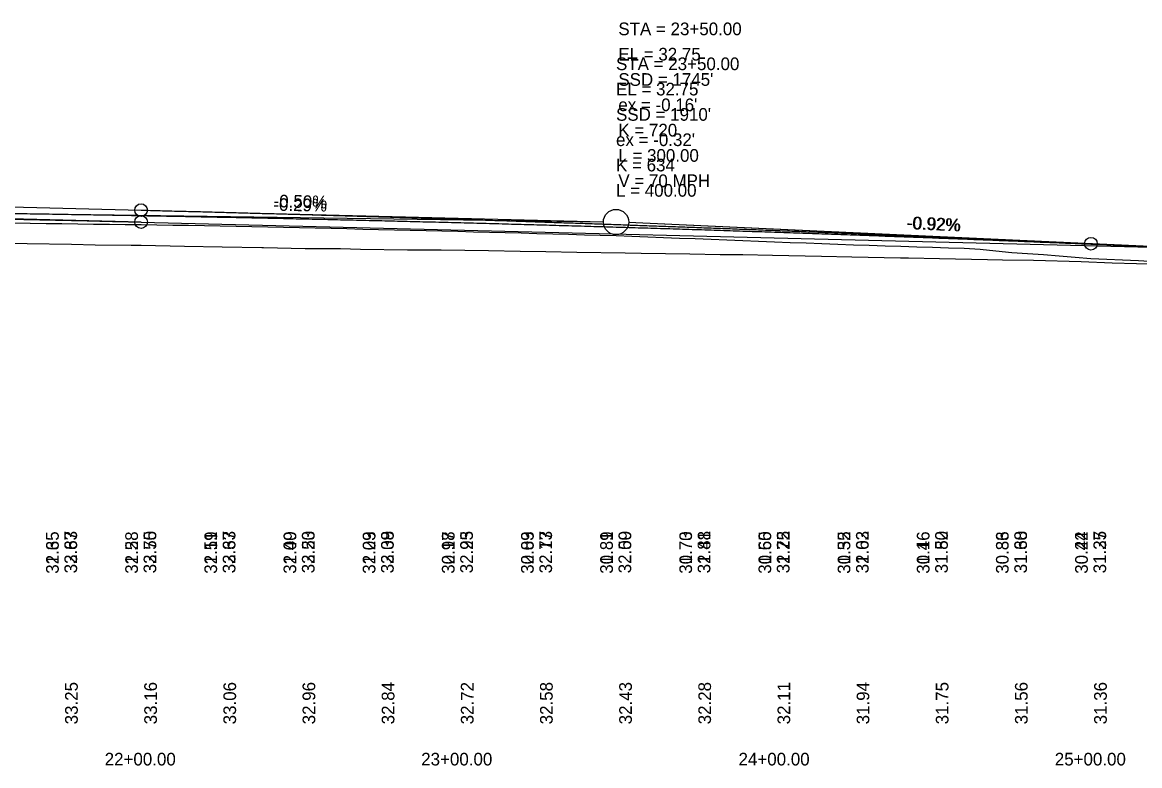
# Model space of a CAD drawing. Extents: x 3880794 to 3915434, y 287517 to 300173.
# Drawn here: x 3882700.8 to 3883053.7, y 296519.7 to 296754.6 of the extents above; entities that cross this region are included whole.
import ezdxf

# ---------------------------------------------------------------- set-up
doc = ezdxf.new("R2010")
doc.units = 0
for name, color, linetype in [('Level 1', 7, 'Continuous'), ('Level 2', 7, 'Continuous'), ('Level 30', 7, 'Continuous'), ('Level 31', 7, 'Continuous'), ('Level 32', 7, 'Continuous')]:
    doc.layers.add(name, color=color, linetype=linetype)

msp = doc.modelspace()

# ---------------------------------------------------------------- linework, layer by layer
at = {"layer": 'Level 1'}
for p, q in [((3882738.3, 296691.51), (3882542.3, 296696.41)), ((3882688.3, 296694.36), (3882884.3, 296691.56)), ((3882738.3, 296691.51), (3883088.3, 296682.76)), ((3883088.3, 296682.34), (3882892.29, 296691.32))]:
    msp.add_line(p, q, dxfattribs=at)
msp.add_lwpolyline([(3882691.39, 296684.85), (3882702.29, 296684.71), (3882716.34, 296684.48), (3882723.78, 296684.35), (3882735.12, 296684.21), (3882738.31, 296684.17), (3882751.98, 296683.92), (3882763.94, 296683.68), (3882776.44, 296683.45), (3882776.96, 296683.44), (3882790.17, 296683.17), (3882801.3, 296683.12), (3882807.64, 296682.98), (3882822.44, 296682.77), (3882832.63, 296682.73), (3882833.04, 296682.73), (3882848.06, 296682.51), (3882858.02, 296682.29), (3882866.12, 296682.17), (3882875.88, 296681.96), (3882891.17, 296681.76), (3882896.22, 296681.65), (3882911.64, 296681.45), (3882921.21, 296681.29), (3882928.3, 296681.2), (3882937.68, 296681.05), (3882953.23, 296680.7), (3882962.8, 296680.54), (3882978.16, 296680.21), (3882980.64, 296680.16), (3882990.44, 296680.02), (3883005.6, 296679.69), (3883010.32, 296679.59), (3883020.14, 296679.45), (3883035.18, 296679.01), (3883044.95, 296678.6), (3883060.37, 296678.16)], dxfattribs=at)
msp.add_circle((3882888.3, 296691.51), 4, dxfattribs=at)
for points in [[(3882338.3, 296690.81), (3882346.3, 296691.03), (3882354.3, 296691.25), (3882362.3, 296691.45), (3882370.3, 296691.65), (3882378.3, 296691.84), (3882386.3, 296692.02), (3882394.3, 296692.19), (3882402.3, 296692.36), (3882410.3, 296692.51), (3882418.3, 296692.66), (3882426.3, 296692.8), (3882434.3, 296692.93), (3882442.3, 296693.05), (3882450.3, 296693.16), (3882458.3, 296693.26), (3882466.3, 296693.36), (3882474.3, 296693.45), (3882482.3, 296693.52), (3882490.3, 296693.59), (3882498.3, 296693.65), (3882506.3, 296693.71), (3882514.3, 296693.75), (3882522.3, 296693.79), (3882530.3, 296693.81), (3882538.3, 296693.83), (3882546.3, 296693.84), (3882554.3, 296693.84), (3882562.3, 296693.84), (3882570.3, 296693.82), (3882578.3, 296693.79), (3882586.3, 296693.76), (3882594.3, 296693.72), (3882602.3, 296693.67), (3882610.3, 296693.61), (3882618.3, 296693.54), (3882626.3, 296693.47), (3882634.3, 296693.38), (3882642.3, 296693.29), (3882650.3, 296693.19), (3882658.3, 296693.08), (3882666.3, 296692.96), (3882674.3, 296692.83), (3882682.3, 296692.7), (3882690.3, 296692.55), (3882698.3, 296692.4), (3882706.3, 296692.24), (3882714.3, 296692.07), (3882722.3, 296691.89), (3882730.3, 296691.7), (3882738.3, 296691.51)], [(3882688.3, 296694.36), (3882696.3, 296694.25), (3882704.3, 296694.13), (3882712.3, 296694), (3882720.3, 296693.87), (3882728.3, 296693.73), (3882736.3, 296693.59), (3882744.3, 296693.44), (3882752.3, 296693.29), (3882760.3, 296693.13), (3882768.3, 296692.97), (3882776.3, 296692.8), (3882784.3, 296692.63), (3882792.3, 296692.45), (3882800.3, 296692.27), (3882808.3, 296692.08), (3882816.3, 296691.89), (3882824.3, 296691.69), (3882832.3, 296691.49), (3882840.3, 296691.28), (3882848.3, 296691.07), (3882856.3, 296690.85), (3882864.3, 296690.63), (3882872.3, 296690.4), (3882880.3, 296690.17), (3882888.3, 296689.93), (3882896.3, 296689.69), (3882904.3, 296689.44), (3882912.3, 296689.19), (3882920.3, 296688.93), (3882928.3, 296688.66), (3882936.3, 296688.4), (3882944.3, 296688.12), (3882952.3, 296687.84), (3882960.3, 296687.56), (3882968.3, 296687.27), (3882976.3, 296686.98), (3882984.3, 296686.68), (3882992.3, 296686.38), (3883000.3, 296686.07), (3883008.3, 296685.75), (3883016.3, 296685.44), (3883024.3, 296685.11), (3883032.3, 296684.78), (3883040.3, 296684.45), (3883048.3, 296684.11), (3883056.3, 296683.77), (3883064.3, 296683.42), (3883072.3, 296683.06), (3883080.3, 296682.7), (3883088.3, 296682.34)]]:
    msp.add_spline(points, degree=3, dxfattribs=at)
at = {"layer": 'Level 2'}
for p, q in [((3882688.3, 296696.51), (3882738.3, 296695.26)), ((3882738.3, 296695.26), (3882884.3, 296691.61)), ((3883038.3, 296684.63), (3882892.29, 296691.32)), ((3883038.3, 296684.63), (3883088.3, 296682.34))]:
    msp.add_line(p, q, dxfattribs=at)
for points in [[(3882698.3, 296691.21), (3882703.3, 296691.15), (3882708.3, 296691.08), (3882713.3, 296691.01), (3882718.3, 296690.95), (3882723.3, 296690.88), (3882728.3, 296690.82), (3882733.3, 296690.75), (3882738.3, 296690.68), (3882743.3, 296690.62), (3882748.3, 296690.55), (3882753.3, 296690.48), (3882758.3, 296690.41), (3882763.3, 296690.3), (3882768.3, 296690.19), (3882773.3, 296690.08), (3882778.3, 296689.97), (3882783.3, 296689.86), (3882788.3, 296689.74), (3882793.3, 296689.63), (3882798.3, 296689.52), (3882803.3, 296689.41), (3882808.3, 296689.3), (3882813.3, 296689.19), (3882818.3, 296689.07), (3882823.3, 296688.96), (3882828.3, 296688.85), (3882833.3, 296688.72), (3882838.3, 296688.58), (3882843.3, 296688.45), (3882848.3, 296688.31), (3882853.3, 296688.17), (3882858.3, 296688.04), (3882863.3, 296687.9), (3882868.3, 296687.76), (3882873.3, 296687.62), (3882878.3, 296687.48), (3882883.3, 296687.34), (3882888.3, 296687.2), (3882893.3, 296687.01), (3882898.3, 296686.82), (3882903.3, 296686.62), (3882908.3, 296686.44), (3882913.3, 296686.25), (3882918.3, 296686.05), (3882923.3, 296685.86), (3882928.3, 296685.66), (3882933.3, 296685.47), (3882938.3, 296685.28), (3882943.3, 296685.08), (3882948.3, 296684.88), (3882953.3, 296684.69), (3882958.3, 296684.5), (3882963.3, 296684.34), (3882968.3, 296684.18), (3882973.3, 296684.02), (3882978.3, 296683.86), (3882983.3, 296683.7), (3882988.3, 296683.54), (3882993.3, 296683.38), (3882998.3, 296683.22), (3883003.3, 296682.96), (3883008.3, 296682.43), (3883013.3, 296681.89), (3883018.3, 296681.58), (3883023.3, 296681.21), (3883028.3, 296680.8), (3883033.3, 296680.39), (3883038.3, 296679.97)], [(3883038.3, 296679.97), (3883043.3, 296679.72), (3883048.3, 296679.51), (3883053.3, 296679.3), (3883058.3, 296679.08)]]:
    msp.add_lwpolyline(points, dxfattribs=at)
for centre, radius in [((3882738.3, 296695.26), 2), ((3882888.3, 296691.51), 4), ((3883038.3, 296684.63), 2)]:
    msp.add_circle(centre, radius, dxfattribs=at)
msp.add_spline([(3882738.3, 296695.26), (3882744.3, 296695.11), (3882750.3, 296694.95), (3882756.3, 296694.8), (3882762.3, 296694.64), (3882768.3, 296694.48), (3882774.3, 296694.31), (3882780.3, 296694.15), (3882786.3, 296693.98), (3882792.3, 296693.81), (3882798.3, 296693.63), (3882804.3, 296693.46), (3882810.3, 296693.28), (3882816.3, 296693.1), (3882822.3, 296692.91), (3882828.3, 296692.73), (3882834.3, 296692.54), (3882840.3, 296692.35), (3882846.3, 296692.15), (3882852.3, 296691.96), (3882858.3, 296691.76), (3882864.3, 296691.56), (3882870.3, 296691.35), (3882876.3, 296691.15), (3882882.3, 296690.94), (3882888.3, 296690.73), (3882894.3, 296690.51), (3882900.3, 296690.3), (3882906.3, 296690.08), (3882912.3, 296689.86), (3882918.3, 296689.63), (3882924.3, 296689.41), (3882930.3, 296689.18), (3882936.3, 296688.95), (3882942.3, 296688.71), (3882948.3, 296688.48), (3882954.3, 296688.24), (3882960.3, 296688), (3882966.3, 296687.75), (3882972.3, 296687.51), (3882978.3, 296687.26), (3882984.3, 296687.01), (3882990.3, 296686.75), (3882996.3, 296686.5), (3883002.3, 296686.24), (3883008.3, 296685.98), (3883014.3, 296685.71), (3883020.3, 296685.45), (3883026.3, 296685.18), (3883032.3, 296684.91), (3883038.3, 296684.63)], degree=3, dxfattribs=at)
at = {"layer": 'Level 31'}
msp.add_circle((3882738.3, 296691.51), 2, dxfattribs=at)

# ---------------------------------------------------------------- texts
at = {"layer": 'Level 2'}
for s, p in [('STA = 23+50.00', (3882889.03, 296750.55)), ('EL = 32.75', (3882889.03, 296742.55)), ("SSD = 1745'", (3882889.03, 296734.55)), ("ex = -0.16'", (3882889.03, 296726.55)), ('K = 720', (3882889.03, 296718.55)), ('L = 300.00', (3882889.03, 296710.55)), ('V = 70 MPH', (3882889.03, 296702.55)), ('22+00.00', (3882726.8, 296519.76)), ('23+00.00', (3882826.77, 296519.76)), ('24+00.00', (3882926.99, 296519.76)), ('25+00.00', (3883026.87, 296519.76))]:
    msp.add_text(s, height=4, dxfattribs=at).set_placement(p)
for s, rotation, p in [('-0.50%', 358.5679, (3882780.1, 296696.21)), ('-0.92%', 357.3758, (3882980.22, 296689.3)), ('33.63', 90, (3882718.09, 296580.49)), ('33.50', 90, (3882743.09, 296580.49)), ('33.37', 90, (3882768.09, 296580.49)), ('33.23', 90, (3882793.09, 296580.49)), ('33.09', 90, (3882818.09, 296580.49)), ('32.93', 90, (3882843.09, 296580.49)), ('32.77', 90, (3882868.09, 296580.49)), ('32.59', 90, (3882893.09, 296580.49)), ('32.41', 90, (3882918.09, 296580.49)), ('32.22', 90, (3882943.09, 296580.49)), ('32.02', 90, (3882968.09, 296580.49)), ('31.82', 90, (3882993.09, 296580.49)), ('31.60', 90, (3883018.09, 296580.49)), ('31.37', 90, (3883043.09, 296580.49))]:
    msp.add_text(s, height=4, rotation=rotation, dxfattribs=at).set_placement(p)
at = {"layer": 'Level 30'}
for s, p in [('31.35', (3882712.3, 296580.35)), ('31.28', (3882737.3, 296580.35)), ('31.19', (3882762.3, 296580.35)), ('31.09', (3882787.3, 296580.35)), ('31.03', (3882812.3, 296580.35)), ('30.98', (3882837.3, 296580.35)), ('30.89', (3882862.3, 296580.35)), ('30.81', (3882887.3, 296580.35)), ('30.73', (3882912.3, 296580.35)), ('30.65', (3882937.3, 296580.35)), ('30.55', (3882962.3, 296580.35)), ('30.46', (3882987.3, 296580.35)), ('30.36', (3883012.3, 296580.35)), ('30.22', (3883037.3, 296580.35))]:
    msp.add_text(s, height=4, rotation=90, dxfattribs=at).set_placement(p)
for s, p in [('22+00.00', (3882726.8, 296519.76)), ('22+00.00', (3882726.8, 296519.76)), ('22+00.00', (3882726.8, 296519.76)), ('23+00.00', (3882826.77, 296519.76)), ('23+00.00', (3882826.77, 296519.76)), ('23+00.00', (3882826.77, 296519.76)), ('24+00.00', (3882926.99, 296519.76)), ('24+00.00', (3882926.99, 296519.76)), ('24+00.00', (3882926.99, 296519.76)), ('25+00.00', (3883026.87, 296519.76)), ('25+00.00', (3883026.87, 296519.76)), ('25+00.00', (3883026.87, 296519.76))]:
    msp.add_text(s, height=4, dxfattribs=at).set_placement(p)
at = {"layer": 'Level 31'}
for s, p in [('STA = 23+50.00', (3882888.3, 296739.51)), ('EL = 32.75', (3882888.3, 296731.51)), ("SSD = 1910'", (3882888.3, 296723.51)), ("ex = -0.32'", (3882888.3, 296715.51)), ('K = 634', (3882888.3, 296707.51)), ('L = 400.00', (3882888.3, 296699.51))]:
    msp.add_text(s, height=4, dxfattribs=at).set_placement(p)
for s, rotation, p in [('-0.29%', 359.1815, (3882780.05, 296695.05)), ('-0.92%', 357.3758, (3882980.01, 296689.31)), ('32.87', 90, (3882718.09, 296580.49)), ('32.75', 90, (3882743.09, 296580.49)), ('32.63', 90, (3882768.09, 296580.49)), ('32.50', 90, (3882793.09, 296580.49)), ('32.38', 90, (3882818.09, 296580.49)), ('32.25', 90, (3882843.09, 296580.49)), ('32.13', 90, (3882868.09, 296580.49)), ('32.00', 90, (3882893.09, 296580.49)), ('31.88', 90, (3882918.09, 296580.49)), ('31.75', 90, (3882943.09, 296580.49)), ('31.63', 90, (3882968.09, 296580.49)), ('31.50', 90, (3882993.09, 296580.49)), ('31.38', 90, (3883018.09, 296580.49)), ('31.25', 90, (3883043.09, 296580.49)), ('33.25', 90, (3882718.3, 296532.76)), ('33.16', 90, (3882743.3, 296532.76)), ('33.06', 90, (3882768.3, 296532.76)), ('32.96', 90, (3882793.3, 296532.76)), ('32.84', 90, (3882818.3, 296532.76)), ('32.72', 90, (3882843.3, 296532.76)), ('32.58', 90, (3882868.3, 296532.76)), ('32.43', 90, (3882893.3, 296532.76)), ('32.28', 90, (3882918.3, 296532.76)), ('32.11', 90, (3882943.3, 296532.76)), ('31.94', 90, (3882968.3, 296532.76)), ('31.75', 90, (3882993.3, 296532.76)), ('31.56', 90, (3883018.3, 296532.76)), ('31.36', 90, (3883043.3, 296532.76))]:
    msp.add_text(s, height=4, rotation=rotation, dxfattribs=at).set_placement(p)
at = {"layer": 'Level 32'}
for s, p in [('32.65', (3882712.3, 296580.35)), ('32.58', (3882737.3, 296580.35)), ('32.51', (3882762.3, 296580.35)), ('32.40', (3882787.3, 296580.35)), ('32.29', (3882812.3, 296580.35)), ('32.17', (3882837.3, 296580.35)), ('32.03', (3882862.3, 296580.35)), ('31.89', (3882887.3, 296580.35)), ('31.70', (3882912.3, 296580.35)), ('31.50', (3882937.3, 296580.35)), ('31.32', (3882962.3, 296580.35)), ('31.16', (3882987.3, 296580.35)), ('30.83', (3883012.3, 296580.35)), ('30.44', (3883037.3, 296580.35))]:
    msp.add_text(s, height=4, rotation=90, dxfattribs=at).set_placement(p)

doc.saveas('drawing.dxf')
